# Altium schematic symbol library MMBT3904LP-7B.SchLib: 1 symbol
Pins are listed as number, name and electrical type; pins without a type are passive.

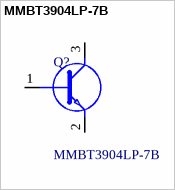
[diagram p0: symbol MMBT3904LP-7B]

## MMBT3904LP-7B
designator Q?
Bipolar Transistors - BJT General Purpose Tran X1-DFN1006-3,10K 40V NPN SMALL SIGNAL TRANSISTOR IN X1-DFN1006-3; Manufacturer_Name: Diodes Inc.; Geometry.Height: 0.53mm
footprint MMBT3904LP7B
pins: 1 B, 2 E, 3 C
